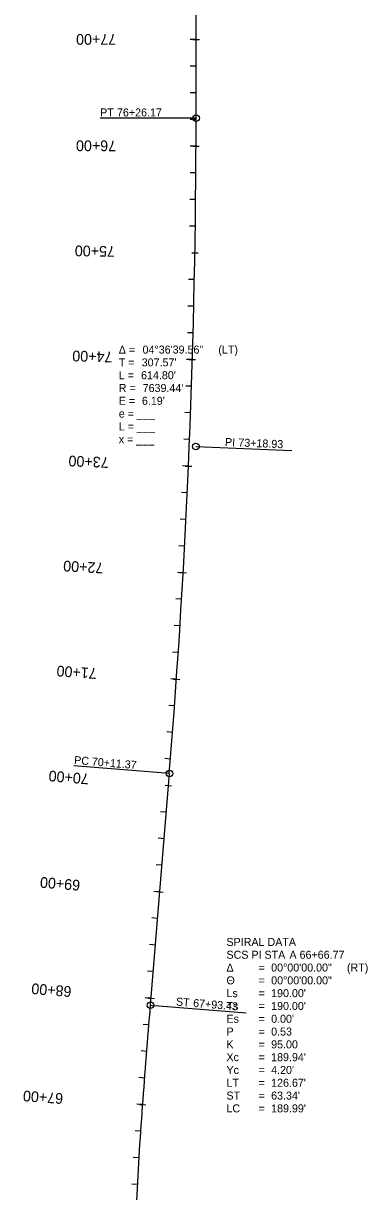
# Model space of a CAD drawing. Extents: x 11526371 to 11527168, y 9590726 to 9599509.
# Drawn here: x 11526380 to 11526703, y 9595127 to 9596222 of the extents above; entities that cross this region are included whole.
import ezdxf

# ---------------------------------------------------------------- set-up
doc = ezdxf.new("R2010")
doc.units = 0
for name, color, linetype in [('Alignment', 7, 'Continuous'), ('Default', 7, 'Continuous'), ('TextAlignment', 7, 'Continuous'), ('TextAlignmentLrg', 7, 'Continuous'), ('TextAlignmentSml', 7, 'Continuous')]:
    doc.layers.add(name, color=color, linetype=linetype)

msp = doc.modelspace()

# ---------------------------------------------------------------- linework, layer by layer
at = {"layer": 'Alignment'}
for p, q in [((11526542.5, 9596132.7), (11526542.9, 9596688)), ((11526499.8, 9595301.3), (11526517.5, 9595518.6))]:
    msp.add_line(p, q, dxfattribs=at)
msp.add_arc((11518903.1, 9596137.1), 7639.4, 355.35561, 359.9666, dxfattribs=at)
msp.add_open_spline([(11526486.5, 9595111.8), (11526487.3, 9595127.6), (11526489, 9595159.3), (11526492.3, 9595206.6), (11526495.9, 9595254), (11526498.5, 9595285.6), (11526499.8, 9595301.3)], degree=3, dxfattribs=at)
at = {"layer": 'Default'}
for p, q in [((11526542.5, 9596132.7), (11526542.9, 9596688)), ((11526499.8, 9595301.3), (11526517.5, 9595518.6))]:
    msp.add_line(p, q, dxfattribs=at)
msp.add_arc((11518903.1, 9596137.1), 7639.4, 355.35561, 359.9666, dxfattribs=at)
at = {"layer": 'TextAlignment'}
for p, q in [((11526542.5, 9596132.7), (11526452.5, 9596132.7)), ((11526452.5, 9596132.7), (11526452.5, 9596132.7)), ((11526542.4, 9595825.1), (11526632.3, 9595821.4)), ((11526632.3, 9595821.4), (11526632.3, 9595821.4)), ((11526517.5, 9595518.6), (11526427.8, 9595525.8)), ((11526427.8, 9595525.8), (11526427.8, 9595525.8)), ((11526499.8, 9595301.3), (11526589.5, 9595294.1)), ((11526589.5, 9595294.1), (11526589.5, 9595294.1))]:
    msp.add_line(p, q, dxfattribs=at)
for centre in [(11526542.5, 9596132.7), (11526542.4, 9595825.1), (11526517.5, 9595518.6), (11526499.8, 9595301.3)]:
    msp.add_circle(centre, 3.12, dxfattribs=at)
at = {"layer": 'TextAlignmentLrg'}
for p, q in [((11526542.6, 9596206.5), (11526537.1, 9596206.5)), ((11526542.5, 9596106.5), (11526537, 9596106.5)), ((11526538.4, 9596006.6), (11526544.5, 9596006.5)), ((11526539.1, 9595906.5), (11526533.6, 9595906.7)), ((11526535.4, 9595806.6), (11526529.9, 9595806.8)), ((11526530.4, 9595706.7), (11526525, 9595707)), ((11526524.1, 9595606.9), (11526518.7, 9595607.3)), ((11526513.5, 9595507.5), (11526519.6, 9595507)), ((11526508.4, 9595407.6), (11526503, 9595408)), ((11526500.3, 9595307.9), (11526494.9, 9595308.3)), ((11526492.5, 9595208.2), (11526487, 9595208.6))]:
    msp.add_line(p, q, dxfattribs=at)
at = {"layer": 'TextAlignmentSml'}
for p, q in [((11526539.5, 9596206.5), (11526545.6, 9596206.5)), ((11526542.6, 9596181.5), (11526537.1, 9596181.5)), ((11526542.6, 9596156.5), (11526537.1, 9596156.5)), ((11526542.5, 9596131.5), (11526537.1, 9596131.5)), ((11526539.4, 9596106.5), (11526545.5, 9596106.5)), ((11526542.3, 9596081.5), (11526536.9, 9596081.5)), ((11526542.1, 9596056.5), (11526536.7, 9596056.6)), ((11526541.8, 9596031.5), (11526536.4, 9596031.6)), ((11526538.4, 9596006.6), (11526544.5, 9596006.5)), ((11526541, 9595981.5), (11526535.5, 9595981.6)), ((11526540.4, 9595956.5), (11526534.9, 9595956.7)), ((11526539.8, 9595931.5), (11526534.3, 9595931.7)), ((11526536, 9595906.6), (11526542.1, 9595906.5)), ((11526538.3, 9595881.6), (11526532.8, 9595881.7)), ((11526537.4, 9595856.6), (11526531.9, 9595856.8)), ((11526536.4, 9595831.6), (11526531, 9595831.8)), ((11526532.3, 9595806.7), (11526538.4, 9595806.5)), ((11526534.3, 9595781.6), (11526528.8, 9595781.9)), ((11526533.1, 9595756.7), (11526527.6, 9595756.9)), ((11526531.8, 9595731.7), (11526526.3, 9595732)), ((11526527.4, 9595706.9), (11526533.5, 9595706.6)), ((11526529, 9595681.8), (11526523.5, 9595682.1)), ((11526527.4, 9595656.8), (11526522, 9595657.2)), ((11526525.8, 9595631.9), (11526520.4, 9595632.2)), ((11526521.1, 9595607.1), (11526527.2, 9595606.7)), ((11526522.3, 9595582), (11526516.9, 9595582.4)), ((11526520.5, 9595557.1), (11526515, 9595557.5)), ((11526518.5, 9595532.1), (11526513.1, 9595532.6)), ((11526513.5, 9595507.5), (11526519.6, 9595507)), ((11526514.5, 9595482.3), (11526509.1, 9595482.7)), ((11526512.5, 9595457.4), (11526507, 9595457.8)), ((11526510.5, 9595432.5), (11526505, 9595432.9)), ((11526505.4, 9595407.8), (11526511.5, 9595407.3)), ((11526506.4, 9595382.6), (11526501, 9595383.1)), ((11526504.4, 9595357.7), (11526498.9, 9595358.2)), ((11526502.4, 9595332.8), (11526496.9, 9595333.2)), ((11526497.3, 9595308.1), (11526503.4, 9595307.6)), ((11526498.3, 9595283), (11526492.9, 9595283.4)), ((11526496.3, 9595258.1), (11526490.9, 9595258.5)), ((11526494.4, 9595233.1), (11526488.9, 9595233.6)), ((11526489.4, 9595208.4), (11526495.5, 9595208)), ((11526490.7, 9595183.3), (11526485.3, 9595183.6)), ((11526489.1, 9595158.3), (11526483.6, 9595158.7)), ((11526487.6, 9595133.4), (11526482.2, 9595133.7))]:
    msp.add_line(p, q, dxfattribs=at)

# ---------------------------------------------------------------- texts
at = {"layer": 'TextAlignment'}
for s, rotation, p in [('PT', 359.9666, (11526452.5, 9596134.4)), ('76+26.17', 359.9666, (11526468.3, 9596134.4)), ('PI ', 357.6611, (11526569.5, 9595825.6)), ('73+18.93', 357.6611, (11526582, 9595825.1)), ('PC', 355.3556, (11526427.9, 9595527.5)), ('70+11.37', 355.3556, (11526444.5, 9595526.1)), ('ST', 355.3556, (11526523.4, 9595301.1)), ('67+93.43', 355.3556, (11526539.5, 9595299.8))]:
    msp.add_text(s, height=7.5, rotation=rotation, dxfattribs=at).set_placement(p)
for s, p in [('Δ = ', (11526470, 9595912.1)), ('04°36\'39.56"', (11526492.3, 9595912.1)), (' (LT)', (11526560.6, 9595912.1)), ('T = ', (11526470, 9595900.1)), ("307.57'", (11526491.5, 9595900.1)), ('L = ', (11526470, 9595888.1)), ("614.80'", (11526490.9, 9595888.1)), ('R = ', (11526470, 9595876.1)), ("7639.44'", (11526492.4, 9595876.1)), ('E = ', (11526470, 9595864.1)), ("6.19'", (11526491.7, 9595864.1)), ('e = ___ ', (11526470, 9595852.1)), ('L = ___', (11526470, 9595840.1)), ('x = ___', (11526470, 9595828.1)), ('SPIRAL DATA', (11526571, 9595356.9)), ('SCS PI STA ', (11526571, 9595344.9)), ('A 66+66.77', (11526630.1, 9595344.9)), ('Δ', (11526571, 9595332.9)), ('= ', (11526601, 9595332.9)), ('00°00\'00.00"', (11526612.9, 9595332.9)), (' (RT)', (11526681.2, 9595332.9)), ('Θ ', (11526571, 9595320.9)), ('= ', (11526601, 9595320.9)), ('00°00\'00.00"', (11526612.9, 9595320.9)), ('Ls', (11526571, 9595308.9)), ('= ', (11526601, 9595308.9)), ("190.00'", (11526612.9, 9595308.9)), ('Ts', (11526571, 9595296.9)), ("190.00'", (11526612.9, 9595296.9)), ('Es', (11526571, 9595284.9)), ('= ', (11526601, 9595296.9)), ("0.00'", (11526612.9, 9595284.9)), ('= ', (11526601, 9595284.9)), ('P', (11526571, 9595272.9)), ('= ', (11526601, 9595272.9)), ('0.53', (11526612.9, 9595272.9)), ('K', (11526571, 9595260.9)), ('= ', (11526601, 9595260.9)), ('95.00', (11526612.9, 9595260.9)), ('Xc', (11526571, 9595248.9)), ('= ', (11526601, 9595248.9)), ("189.94'", (11526612.9, 9595248.9)), ('Yc', (11526571, 9595236.9)), ('= ', (11526601, 9595236.9)), ("4.20'", (11526612.9, 9595236.9)), ('LT', (11526571, 9595224.9)), ('= ', (11526601, 9595224.9)), ("126.67'", (11526612.9, 9595224.9)), ('ST ', (11526571, 9595212.9)), ('= ', (11526601, 9595212.9)), ("63.34'", (11526612.9, 9595212.9)), ('LC', (11526571, 9595200.9)), ('= ', (11526601, 9595200.9)), ("189.99'", (11526612.9, 9595200.9))]:
    msp.add_text(s, height=7.5, dxfattribs=at).set_placement(p)
at = {"layer": 'TextAlignmentLrg'}
for s, rotation, p in [('75+00', 179.0204, (11526466.5, 9596012.8)), ('70+00', 175.3556, (11526442.2, 9595518.3))]:
    msp.add_text(s, height=10.02, rotation=rotation, dxfattribs=at).set_placement(p)
at = {"layer": 'TextAlignmentSml'}
for s, rotation, p in [('77+00', 179.9666, (11526467.6, 9596211.6)), ('76+00', 179.7704, (11526467.5, 9596111.8)), ('75+00', 179.0204, (11526466.5, 9596012.8)), ('74+00', 178.2704, (11526464.2, 9595913.8)), ('73+00', 177.5204, (11526460.7, 9595814.9)), ('72+00', 176.7704, (11526455.8, 9595716)), ('71+00', 176.0204, (11526449.6, 9595617.1)), ('70+00', 175.3556, (11526442.2, 9595518.3)), ('69+00', 175.3556, (11526434.1, 9595418.6)), ('68+00', 175.3556, (11526426, 9595318.9)), ('67+00', 175.815, (11526418.1, 9595218.7))]:
    msp.add_text(s, height=10.02, rotation=rotation, dxfattribs=at).set_placement(p)

doc.saveas('drawing.dxf')
